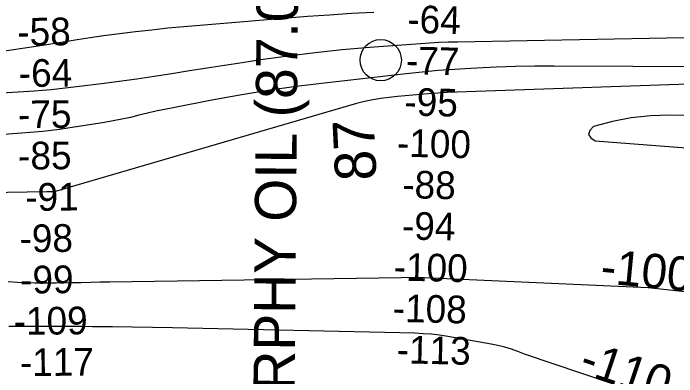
# Model space of a CAD drawing. Extents: x 3704301 to 3742427, y 506229 to 532009.
# Drawn here: x 3719911 to 3721518, y 519827 to 520706 of the extents above; entities that cross this region are included whole.
import ezdxf

# ---------------------------------------------------------------- set-up
doc = ezdxf.new("R2010")
doc.units = 0
for name, color, linetype in [('V-CHAN-NAID', 7, 'Continuous'), ('V-RIVR-IDEN', 7, 'Continuous'), ('V-RIVR-MILE', 7, 'Continuous'), ('V-RIVR-RANG', 7, 'Continuous'), ('V-TOPO-MAJR', 7, 'Continuous'), ('V-TOPO-MAJR-IDEN', 7, 'Continuous'), ('V-TOPO-MINR', 7, 'Continuous'), ('V-TOPO-MINR-IDEN', 7, 'Continuous')]:
    doc.layers.add(name, color=color, linetype=linetype)

msp = doc.modelspace()

# ---------------------------------------------------------------- linework, layer by layer
at = {"layer": 'V-RIVR-MILE'}
msp.add_circle((3720801.1, 520592.8), 50, dxfattribs=at)
at = {"layer": 'V-TOPO-MAJR'}
for points in [[(3721805.7, 520458.3), (3721501.5, 520459.9), (3721454.7, 520458), (3721408.2, 520453.2), (3721362.5, 520444.3), (3721317.1, 520432.4), (3721307.9, 520422.5), (3721304.5, 520413.2), (3721309.9, 520405), (3721321, 520397.3), (3721751.4, 520364.6)], [(3721984.5, 519983.3), (3721449.3, 520042.1), (3720889.2, 520066.4), (3720850.8, 520066.3), (3720144.8, 520055.5), (3720121.5, 520055.1), (3720098.3, 520054.7), (3720075, 520054.2), (3720051.8, 520053.7), (3720014.8, 520052.8), (3720010.1, 520052.7), (3720005.3, 520052.6), (3720000.6, 520052.6), (3719995.8, 520052.7), (3719962.5, 520053.2), (3719941.1, 520053.8), (3719919.7, 520054.7), (3719898.3, 520056.1)]]:
    msp.add_lwpolyline(points, dxfattribs=at)
at = {"layer": 'V-TOPO-MINR'}
for points in [[(3720784, 520708.2), (3720730.6, 520705.5), (3720677.2, 520702), (3720623.9, 520698.1), (3720363.1, 520676.9), (3720324.1, 520673.6), (3720285, 520669.9), (3720246.1, 520665.8), (3720207.1, 520661.4), (3720193.5, 520659.9), (3720161.4, 520655.8), (3720129.3, 520651.5), (3720097.3, 520646.8), (3720065.3, 520641.7), (3720031.9, 520636.2), (3720016.7, 520633.8), (3720001.4, 520631.3), (3719986.2, 520629), (3719971, 520626.7), (3719796.7, 520601.2)], [(3721551.2, 520646.5), (3721493.3, 520645.7), (3720987.5, 520636.6), (3720964.9, 520636), (3720942.3, 520635.2), (3720919.7, 520633.9), (3720897.1, 520632.4), (3720773.7, 520623.2), (3720707.8, 520617.5), (3720642, 520610.8), (3720576.4, 520602.6), (3720510.9, 520593.4), (3720465.3, 520586.5), (3720422.7, 520579.9), (3720380.1, 520573.3), (3720337.6, 520566.6), (3720295, 520559.8), (3720252.4, 520553.2), (3720209.8, 520547), (3720167.1, 520541.1), (3720124.4, 520535.7), (3720043.3, 520525.7), (3720022.7, 520523.4), (3720002.1, 520521.3), (3719981.5, 520519.6), (3719960.9, 520518.1), (3719385.7, 520482.3)], [(3721794, 520576.1), (3721221.4, 520578.2), (3721174.5, 520578), (3721127.7, 520577.3), (3721080.9, 520575.7), (3721034.1, 520573.7), (3721018.7, 520572.9), (3720979.7, 520570.5), (3720940.6, 520567.7), (3720901.7, 520564.1), (3720862.7, 520560), (3720664.8, 520537.5), (3720596.3, 520529), (3720527.9, 520519.3), (3720459.8, 520508.1), (3720391.8, 520495.9), (3720297.8, 520477.8), (3720277, 520473.6), (3720256.3, 520469.2), (3720235.6, 520464.4), (3720215, 520459.3), (3720194.4, 520454.4), (3720173.7, 520449.8), (3720152.9, 520445.8), (3720132, 520442.2), (3720043, 520427.8), (3720022.9, 520424.9), (3720002.8, 520422.2), (3719982.6, 520420.1), (3719962.3, 520418.3), (3719518.6, 520384.7)], [(3721663.8, 520538.4), (3720961.9, 520514.2), (3720950.5, 520513.7), (3720939.1, 520513.1), (3720927.7, 520512.3), (3720916.4, 520511.4), (3720841.9, 520504.7), (3720821.8, 520502.5), (3720801.7, 520499.8), (3720781.7, 520496.4), (3720761.8, 520492.5), (3720742.1, 520488), (3720010, 520274.2), (3720003.8, 520274.2), (3719997.7, 520274.2), (3719991.6, 520274.1), (3719848.4, 520271.6)], [(3721772.4, 519671), (3721149.5, 519881), (3721133.7, 519887.3), (3721117.8, 519893), (3721101.6, 519898), (3721085.2, 519902), (3721068.6, 519905.4), (3720963.4, 519923.8), (3720943.7, 519926.8), (3720923.9, 519929.2), (3720904, 519930.7), (3720884.1, 519931.6), (3720296.4, 519944.8), (3720248, 519945.8), (3720199.6, 519946.6), (3720151.2, 519947.2), (3720102.8, 519947.6), (3720076.7, 519947.8), (3720041.4, 519948), (3720006, 519948.1), (3719970.6, 519948.3), (3719935.3, 519948.4), (3719899.9, 519948.3)]]:
    msp.add_lwpolyline(points, dxfattribs=at)

# ---------------------------------------------------------------- texts
at = {"layer": 'V-CHAN-NAID'}
msp.add_text('MURPHY OIL (87.0)', height=100, rotation=89.5225, dxfattribs=at).set_placement((3720590.8, 519584.7))
at = {"layer": 'V-RIVR-IDEN'}
msp.add_text('87', height=100, rotation=92.8266, dxfattribs=at).set_placement((3720791.2, 520303.2))
at = {"layer": 'V-RIVR-RANG'}
for s, rotation, p in [('-64', 358.6615, (3720864.8, 520658.9)), ('-58', 0.5232, (3719920.6, 520627.8)), ('-77', 358.6615, (3720861.5, 520558.9)), ('-64', 0.5232, (3719924.2, 520527.8)), ('-95', 358.6615, (3720857.8, 520459)), ('-75', 0.5232, (3719922.4, 520427.8)), ('-100', 358.6615, (3720839.7, 520359.4)), ('-85', 0.5232, (3719922.6, 520327.8)), ('-88', 358.6615, (3720852.7, 520259)), ('-91', 0.5232, (3719939.9, 520227.9)), ('-94', 358.6615, (3720851.9, 520159)), ('-98', 0.5232, (3719926, 520127.8)), ('-100', 358.6615, (3720831.9, 520059.5)), ('-99', 0.5232, (3719927.5, 520027.8)), ('-108', 358.6615, (3720829.6, 519959.5)), ('-109', 0.5232, (3719911.8, 519927.7)), ('-113', 358.6615, (3720839.2, 519859.3)), ('-117', 0.5232, (3719927, 519827.8))]:
    msp.add_text(s, height=67, rotation=rotation, dxfattribs=at).set_placement(p)
at = {"layer": 'V-TOPO-MAJR-IDEN'}
msp.add_text('-100', height=83, rotation=354.4814, dxfattribs=at).set_placement((3721331.6, 520053.5))
at = {"layer": 'V-TOPO-MINR-IDEN'}
msp.add_text('-110', height=83, rotation=341.3724, dxfattribs=at).set_placement((3721278.4, 519837.5))

doc.saveas('drawing.dxf')
